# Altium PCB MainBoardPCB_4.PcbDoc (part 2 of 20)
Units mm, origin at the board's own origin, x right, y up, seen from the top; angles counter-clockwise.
Board outline 333.63 x 349.38 mm, 16 copper layers (L1, L2 (GND), L3 (Sign), L4 (GND), L5 (Sign), L6 (PWR/GND), L7(PWR/GND), L8 (Plane_GND), L9 (PWR/GND), L10 (PWR/GND), L11 (PWR/GND), L12 (Sign), L13 (GND), L14 (Sign), L15 (GND), L16), stack 2.502 mm thick; 2205 components, 1648 nets, 8314 pads, 3172 vias.
Unrouted connection lines stored in the file: 5141.
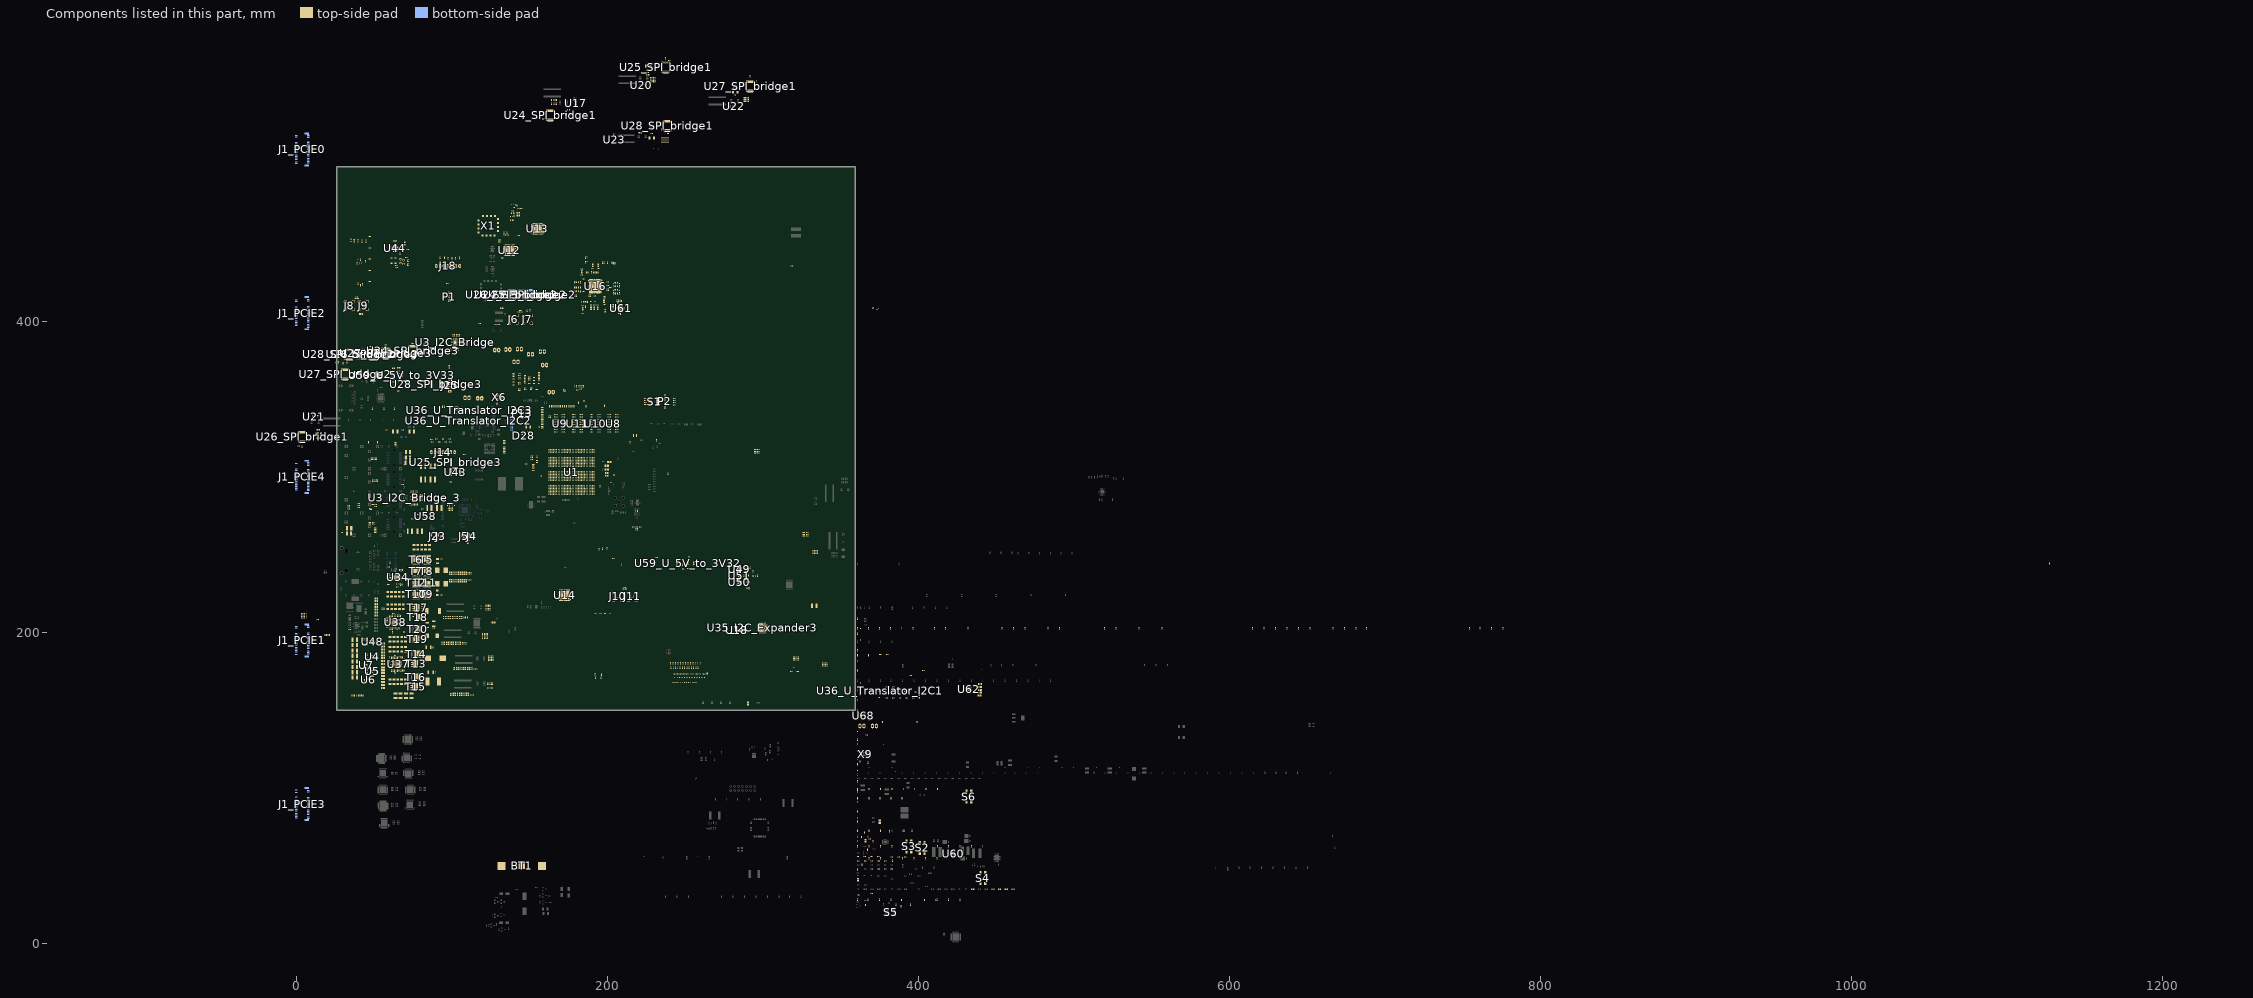
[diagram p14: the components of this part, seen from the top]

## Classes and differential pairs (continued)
differential pair class Diff_100: B223_Rx0 B223_Rx1 B223_Rx2 B223_Rx3 B223_Tx0_to_C B223_Tx0C_to_B B223_Tx1_to_C B223_Tx1C_to_B B223_Tx2_to_C B223_Tx2C_to_B B223_Tx3_to_C B223_Tx3C_to_B B224_Rx0 B224_Rx1 B224_Rx2 B224_Rx3 B224_Tx0_to_C B224_Tx0C_to_B B224_Tx1_to_C B224_Tx1C_to_B B224_Tx2_to_C B224_Tx2C_to_B B224_Tx3_to_C B224_Tx3C_to_B B225_Rx0 B225_Rx1 B225_Rx2 B225_Rx3 B225_Tx0_to_C B225_Tx0C_to_B B225_Tx1_to_C B225_Tx1C_to_B B225_Tx2_to_C B225_Tx2C_to_B B225_Tx3_to_C B225_Tx3C_to_B Bank223_MGTREF0_C Bank223_MGTREF1_C Bank224_MGTREF0_C Bank224_MGTREF1_C Bank225_MGTREF0_C Bank225_MGTREF1_C Bank505_MGTRREF0_C Bank505_MGTRREF2_C Bank505_MGTRREF3_C CLK_100 CLK_Fanout_In CLK_GTR_T1 CLK_GTR_T2 CLK_GTR_T3 CLK_Hi_Rail1 CLK_Hi_Rail1_SysRef CLK_Hi_Rail2 CLK_Hi_Rail2_SysRef CLK_M_OSC_In CLK_NVME_Conn CLK_Q223_T1 CLK_Q224_T1 CLK_Q225_T1 CLK_Q226_T1 CLK_SMA0 CLK_SMA0_C CLK_SMA1 CLK_SMA1_C CLK_SMA2 CLK_SMA2_C Data_2_RX_PCIE0 Data_2_RX_PCIE1 Data_2_RX_PCIE2 Data_2_RX_PCIE3 Data_2_TX_PCIE0 Data_2_TX_PCIE1 Data_2_TX_PCIE2 Data_2_TX_PCIE3 Data_3_RX_PCIE0 Data_3_RX_PCIE1 Data_3_RX_PCIE2 Data_3_RX_PCIE3 Data_3_TX_PCIE0 Data_3_TX_PCIE1 Data_3_TX_PCIE2 Data_3_TX_PCIE3 LTC6952_1_REF LTC6952_2_REF LTC6952_2_REF_SMA LTC6952_3_REF LTC6952_3_REF_SMA NVME_C_RX_O NVME_C_TX_1 NVME_C_TX_O NVMe_CLK NVMe_Rx_0 NVMe_Rx_1 NVMe_Tx_0 NVMe_Tx_1 Osc_in_Si53323_2 OSC_Out_DIV PCIE0_CLK PCIE0_Sync PCIE0_SysRef PCIE0_SysRef_FPGA PCIE1_CLK PCIE1_Sync PCIE1_SysRef PCIE1_SysRef_FPGA PCIE2_CLK PCIE2_Sync PCIE2_SysRef PCIE2_SysRef_FPGA PCIE3_CLK PCIE3_Sync PCIE3_SysRef PCIE3_SysRef_FPGA PCIE4_CLK PCIE4_Sync PCIE4_SysRef PCIE4_SysRef_FPGA RefClk_Si53323 SFP0_Rx SFP0_Tx SFP1_Rx SFP1_Tx SFP2_Rx SFP2_Tx SFP3_Rx SFP3_Tx SGMI_C_Rx SGMI_C_Tx SGMI_CLK_C_Out SGMI_CLK_Out SGMI_Rx SGMI_Tx Si53323_1_Q1 Si53323_1_Q2 Si53323_1_Q2_LVDS Si53323_2_CLK1 Si53323_2_Q1 Si53323_2_Q2 Si53323_2_Q2_LVDS SYNC_PCIE0 SYNC_PCIE1 SYNC_PCIE2 SYNC_PCIE3 SYNC_PCIE4 SYSREF_PCIE0 SYSREF_PCIE1 SYSREF_PCIE2 SYSREF_PCIE3 SYSREF_PCIE4 TD_A TD_B TD_C TD_D WR_LMK_CLK_HF1 WR_LMK_CLK_HF2 WR_LMK_CLK_IN WR_Source_CLK
channel class Translator_I2C: U_Translator_I2C1 U_Translator_I2C2 U_Translator_I2C3
channel class 5V_to_3V3: 5V_to_3V3_for_FTDI U_5V_to_3V32 U_5V_to_3V33
net class SYSREF: PCIE0_SysRef_N PCIE0_SysRef_P PCIE1_SysRef_N PCIE1_SysRef_P PCIE2_SysRef_N PCIE2_SysRef_P PCIE3_SysRef_N PCIE3_SysRef_P PCIE4_SysRef_N PCIE4_SysRef_P
net class Distr_to_Conn: PCIE0_CLK_P PCIE1_CLK_P PCIE2_CLK_P PCIE3_CLK_P PCIE4_CLK_P
net class SFP_diff: SFP0_Rx_N SFP0_Rx_P SFP0_Tx_N SFP0_Tx_P SFP1_Rx_N SFP1_Rx_P SFP1_Tx_N SFP1_Tx_P SFP2_Rx_N SFP2_Rx_P SFP2_Tx_N SFP2_Tx_P SFP3_Rx_N SFP3_Rx_P SFP3_Tx_N SFP3_Tx_P
net class Conn_to_C: B223_Tx0_to_C_N B223_Tx0_to_C_P B223_Tx1_to_C_N B223_Tx1_to_C_P B223_Tx2_to_C_N B223_Tx2_to_C_P B223_Tx3_to_C_N B223_Tx3_to_C_P B224_Tx0_to_C_N B224_Tx0_to_C_P B224_Tx1_to_C_N B224_Tx1_to_C_P B224_Tx2_to_C_N B224_Tx2_to_C_P B224_Tx3_to_C_N B224_Tx3_to_C_P B225_Tx0_to_C_N B225_Tx0_to_C_P B225_Tx1_to_C_N B225_Tx1_to_C_P B225_Tx2_to_C_N B225_Tx2_to_C_P B225_Tx3_to_C_N B225_Tx3_to_C_P Data_2_TX_PCIE0_N Data_2_TX_PCIE0_P Data_2_TX_PCIE1_N Data_2_TX_PCIE1_P Data_2_TX_PCIE2_N Data_2_TX_PCIE2_P Data_2_TX_PCIE3_N Data_2_TX_PCIE3_P Data_3_TX_PCIE0_N Data_3_TX_PCIE0_P Data_3_TX_PCIE1_N Data_3_TX_PCIE1_P Data_3_TX_PCIE2_N Data_3_TX_PCIE2_P Data_3_TX_PCIE3_N Data_3_TX_PCIE3_P
net class C_to_Bank225: B225_Tx0C_to_B_N B225_Tx0C_to_B_P B225_Tx1C_to_B_N B225_Tx1C_to_B_P B225_Tx2C_to_B_N B225_Tx2C_to_B_P B225_Tx3C_to_B_N B225_Tx3C_to_B_P
net class C_to_Bank224: B224_Tx0C_to_B_N B224_Tx0C_to_B_P B224_Tx1C_to_B_N B224_Tx1C_to_B_P B224_Tx2C_to_B_N B224_Tx2C_to_B_P B224_Tx3C_to_B_N B224_Tx3C_to_B_P
net class C_to_Bank223: B223_Rx0_N B223_Rx0_P B223_Rx1_N B223_Rx1_P B223_Rx2_N B223_Rx2_P B223_Rx3_N B223_Rx3_P B223_Tx0C_to_B_N B223_Tx0C_to_B_P B223_Tx1C_to_B_N B223_Tx1C_to_B_P B223_Tx2C_to_B_N B223_Tx2C_to_B_P B223_Tx3C_to_B_N B223_Tx3C_to_B_P
net class Bank_to_Conn: B223_Rx0_N B223_Rx0_P B223_Rx1_N B223_Rx1_P B223_Rx2_N B223_Rx2_P B223_Rx3_N B223_Rx3_P B224_Rx0_N B224_Rx0_P B224_Rx1_N B224_Rx1_P B224_Rx2_N B224_Rx2_P B224_Rx3_N B224_Rx3_P B225_Rx0_N B225_Rx0_P B225_Rx1_N B225_Rx1_P B225_Rx2_N B225_Rx2_P B225_Rx3_N B225_Rx3_P Data_2_RX_PCIE0_N Data_2_RX_PCIE0_P Data_2_RX_PCIE1_N Data_2_RX_PCIE1_P Data_2_RX_PCIE2_N Data_2_RX_PCIE2_P Data_2_RX_PCIE3_N Data_2_RX_PCIE3_P Data_3_RX_PCIE0_N Data_3_RX_PCIE0_P Data_3_RX_PCIE1_N Data_3_RX_PCIE1_P Data_3_RX_PCIE2_N Data_3_RX_PCIE2_P Data_3_RX_PCIE3_N Data_3_RX_PCIE3_P
component class U_Translator_I2C3: TP60_U_Translator_I2C3 TP61_U_Translator_I2C3 U36_U_Translator_I2C3
component class U_Translator_I2C2: TP60_U_Translator_I2C2 TP61_U_Translator_I2C2 U36_U_Translator_I2C2
component class U_Translator_I2C1: TP60_U_Translator_I2C1 TP61_U_Translator_I2C1 U36_U_Translator_I2C1
component class U_TPS7A88_5V_Dual_3: C572 C573 C574 C575 C576 C577 C578 C579 R436 R437 R438 R439 R440 R441 U61
component class U_LT3042_12V_5V_LNLDO: C580 C581 C582 C583 C584 FB34 R442 R443 R444 R445 U62
component class U_ADP1741_3: C568 C569 C570 C571 FB33 R433 R434 U60
component class U_5V_to_3V33: C563_U_5V_to_3V33 C564_U_5V_to_3V33 C565_U_5V_to_3V33 C566_U_5V_to_3V33 C567_U_5V_to_3V33 R430_U_5V_to_3V33 R431_U_5V_to_3V33 R432_U_5V_to_3V33 U59_U_5V_to_3V33
component class U_5V_to_3V32: C563_U_5V_to_3V32 C564_U_5V_to_3V32 C565_U_5V_to_3V32 C566_U_5V_to_3V32 C567_U_5V_to_3V32 R430_U_5V_to_3V32 R431_U_5V_to_3V32 R432_U_5V_to_3V32 U59_U_5V_to_3V32
component class SPI_bridge3: R231_SPI_bridge3 R232_SPI_bridge3 R233_SPI_bridge3 R234_SPI_bridge3 R235_SPI_bridge3 R236_SPI_bridge3 R237_SPI_bridge3 R238_SPI_bridge3 R239_SPI_bridge3 R240_SPI_bridge3 TP50_SPI_bridge3 TP51_SPI_bridge3 TP52_SPI_bridge3 TP53_SPI_bridge3 TP56_SPI_bridge3 TP57_SPI_bridge3 TP58_SPI_bridge3 TP59_SPI_bridge3 U24_SPI_bridge3 U25_SPI_bridge3 U26_SPI_bridge3 U27_SPI_bridge3 U28_SPI_bridge3
component class Ram_Power: C219 C220 C221 C222 C223 C224 C225 C226 C227 C228 C229 C230 C231 C232 C233 C234 C235 C236 C237 C238 C239 C240 C241 C242 C243 C244 C245 C246 C247 C248 C249 C250 C251 C252 C253 C254 C255 C256 C257 C258 C259 C260 C261 C262 C263 C264 C265 C266 C782 C783 C784 C785 C786 C787 C788 C789 R165 R166 R167 R168 R169 R170 R171 R172
component class PS_Config: C531 C532 C533 C534 C535 C536 D5 D6 D7 D8 D9 D10 D11 D12 P2 P3 P4 P5 R346 R347 R348 R349 R350 R351 R352 R353 R354 R355 R356 R357 R358 R359 R360 R361 R367 R368 R369 R370 R371 R372 R373 R374 R375 R716 R717 R718 R719 R720 S1 S2 S3 S4 U43 U44 X5 X6
component class IMU: C561 C562 R425 R426 R429 R600 R601 U58
component class GTR: C525 C526 C527 C528 C529 C530 C649 C651 C653 C677 C715 C716 C717 C718 R69 R70 R126
component class "Bank 225": C291 C292 C293 C294 C295 C296 C297 C298 C299 C300 C301 C302
component class "Bank 224": C279 C280 C281 C282 C283 C284 C285 C286 C287 C288 C289 C290
component class "Bank 223": C267 C268 C269 C270 C271 C272 C273 C274 C275 C276 C277 C278
component class U_Power_Ethernet: C550 C551 C552 C553 C554 C555 C654 C655 C656 C657 R391 R392 R393 R394 R396 R397 R399 R632 R633 R634 U49 U50 U51 U68
component class U_Power_ADP1850_Dual_2: C430 C431 C432 C433 C434 C435 C436 C437 C438 C439 C440 C441 C442 C443 C444 C445 C446 C447 C448 C449 C450 C451 C452 C453 C454 C455 C456 C457 C458 C459 C460 C461 C462 C463 C464 C465 C466 C467 C468 C469 C470 C548 C549 C645 C646 C647 C648 C650 C652 L19 L20 R302 R303 R306 R307 R310 R312 R313 R314 R315 R316 R317 R318 R625 R626 R627 R628 R629 R631 R686 R687 T17 T18 T19 T20 U38
component class U_HI_Curr_ADP1850_3: C389 C390 C391 C392 C393 C394 C395 C396 C397 C398 C399 C400 C401 C402 C403 C404 C405 C406 C407 C408 C409 C410 C411 C412 C413 C414 C415 C416 C417 C418 C419 C420 C421 C422 C423 C424 C425 C426 C427 C428 C429 C637 C638 C639 C640 C641 C642 C643 C644 L11 L12 R285 R287 R288 R289 R290 R292 R293 R294 R295 R296 R297 R298 R299 R300 R619 R620 R621 R622 R623 R624 T13 T14 T15 T16 U37
component class "Zasilanie CLK": C55 C56 C57 C58 C59 C60 C61 C62 C63 C64 C65 C66 C67 C68 C69 C70 C71 C72 C73 C74 C75 C76 C77 C78 C79 C80 C81 C82 C83 C84 C85 C86 C87 C88 C89 C90 C91 C92 C93 C94 C95 C96 C97 C98 C99 C100 C101 C102 C103 C104 C105 C106 C107 C108 C109 C110 C111 C112 C113 C114 C115 C116 C117 C118 C119 C120 C121 C122 C123 C124 C125 C126 C127 C128 C129 C130 C131 C132 C133 C134 C135 C136 C137 C138 C139 C140 C141 C142 C143 C144 C145 C146 C147 C148 C149 C150 C151 C152 C153 C154 C155 C156 C157 C158 C159 C160 C161 C162 C163 C164 C165 C166 C167 C168 C169 C170 C171 C172 C173 C174 C175 C176 C177 C178 C179 C180 C181 C182 C183 C184 C185 C186 C187 C188 C189 C190 C191 C192 C193 C194 C195 C196 C197 C198 C199 C200 C201 C202 C203 C204 C205 C206 FB2 FB3 FB4 FB5 FB6 FB7 FB8 FB9 FB10 FB11 FB12 FB13 FB14 FB15 FB16 FB17 FB18 FB19 FB20 FB21 FB22 FB35 FB36 R738 R739 R740 R741 R742 R743 U16
component class PowerSelector: C4 C5 C6 C7 C8 C9 C10 C11 C12 C13 C14 C15 C16 C17 C18 C19 C20 C21 C22 C23 C24 C25 C26 C27 C28 C29 C30 C31 C32 C33 C34 C35 C766 C767 C768 C769 C770 C771 C772 C773 C774 C775 C776 C777 C778 C779 C780 C781 R11 R12 R13 R15 R17 R18 R19 R20 R21 R23 R25 R26 R27 R28 R29 R30 R630 R677 R678 R679 R680 R681 R682 R683 R684 R685 U4 U5 U6 U7 U48
channel class SPI_Muxes: SPI_bridge1 SPI_bridge2
channel class I2C_Expander: I2C_Expander4 I2C_Expander5
component class XilinxPower: B1 C627 C628 C629 C630 C631 C632 D28 FB38 FB39 FB40 FB41 FB42 J29 J30 R173 R276 R279 R282 R283 R286 R693 R694 R695 R696
component class "Xilinx Linux": J12 J13 J14 J15 J16 J17 J18 J19 J20 J21 J22 J23 J24 J25 P1 P13 R83 R84 R85 R86 R87 R88 R89 R90 R91 R92 R93 R94 R95 R96 R97 R98 R99 R100 R101 R102 R103 R104 R105 R106 R107 R108 R109 R110 R111 R112 R115 R116 R117 R118 R119 R120 R121 R122 R123 R362 R675 R737 R768 R769 R770 R771 R772 R773 R774 R775 R776 R777 R778 R779 R780 R781 R782 R783 R784 R785 R786 R787 R788 R789 R790 R791 R792 R793 R794 R795 R796 R797 R798 R799 R800 R801 R802 R803 R804 R805 R806 R807 R808 R809 R810 R811 R812 R813 R814 R815 R816 TP33 TP34 TP35 TP36 TP37 TP38 TP39 TP40 TP41 TP42
component class "WR CLK": C588 C589 C590 C591 C592 FB37 R1 R2 R125 R127 R128 R129 R130 R131 R132 R133 R134 R139 R311 R366 R498 R499 R540 R543 R544 R545 R692 S6 X9
component class U_HI_Curr_ADP1850_1: C345 C346 C347 C348 C349 C350 C351 C352 C353 C356 C357 C358 C359 C360 C361 C362 C363 C364 C365 C366 C367 C368 C369 C370 C371 C372 C373 C374 C375 C376 C377 C378 C379 C380 C381 C382 C383 C384 C385 C386 C387 C388 C633 C634 C635 C636 L9 L10 R268 R271 R272 R273 R275 R277 R278 R280 R610 R611 R612 R613 R614 R615 R616 T5 T6 T7 T8 T9 T10 T11 T12 U34
component class SPI_bridge2: R231_SPI_bridge2 R232_SPI_bridge2 R233_SPI_bridge2 R234_SPI_bridge2 R235_SPI_bridge2 R236_SPI_bridge2 R237_SPI_bridge2 R238_SPI_bridge2 R239_SPI_bridge2 R240_SPI_bridge2 TP50_SPI_bridge2 TP51_SPI_bridge2 TP52_SPI_bridge2 TP53_SPI_bridge2 TP54_SPI_bridge2 TP55_SPI_bridge2 TP56_SPI_bridge2 TP57_SPI_bridge2 TP58_SPI_bridge2 TP59_SPI_bridge2 U24_SPI_bridge2 U25_SPI_bridge2 U26_SPI_bridge2 U27_SPI_bridge2 U28_SPI_bridge2
component class SPI_bridge1: R231_SPI_bridge1 R232_SPI_bridge1 R233_SPI_bridge1 R234_SPI_bridge1 R235_SPI_bridge1 R236_SPI_bridge1 R237_SPI_bridge1 R238_SPI_bridge1 R239_SPI_bridge1 R240_SPI_bridge1 TP53_SPI_bridge1 TP56_SPI_bridge1 TP57_SPI_bridge1 TP58_SPI_bridge1 TP59_SPI_bridge1 U24_SPI_bridge1 U25_SPI_bridge1 U26_SPI_bridge1 U27_SPI_bridge1 U28_SPI_bridge1
component class SFP3: C215 C216 C217 C218 L7 L8 R155 R156 R157 R158 R161 R162 R163 R164
component class SFP2: C211 C212 C213 C214 L5 L6 R145 R146 R147 R148 R151 R152 R153 R154
component class SFP1: C207 C208 C209 C210 L3 L4 R135 R136 R137 R138 R141 R142 R143 R144
component class Ram: C36 R31 R32 R33 R34 R35 R36 R37 R38 R39 R40 R41 R42 R43 R44 R45 R46 R47 R48 R49 R50 R51 R52 R53 R54 R55 R56 R57 R58 R59 R60 R61 R62 R63 R64 U8 U9 U10 U11
component class Power4HighSpeed: R174 R175 R176 R177 R178 R179 R180 R181 R182 R183 R184 R185 R186 R187 R188 R189 R190 R191 R192 R193 R194 R195 R196 R197 R198 R199 R200 R201 R202 R203 R204 R205 R206 R207 R208 R209 R210 R211 R213 R215 R217 R219 R221 R222 R228 R602 R603 R604 R605 R606 U17 U20 U21 U22 U23
component class I2C_Expander3: C311_I2C_Expander3 U35_I2C_Expander3
component class Ext_GPIO: R241 R242 R243 R244 R281 R400 R428 R492 R493 R494 R495 R496 R497 R500 R501 R502 R503 R504 R505 R508 R509 R510 R511 R512 R513 R516 R517 R518 R519 R520 R521 R524 R525 R526 R527 R528 R529 R599 R697 R698 R699 R700 R701 R702 R703 R704 R705 R706 R707 R708 R832 R833 R834 R835 R836 R837 R838 R839 R840 R841 TP62 TP63 TP64 TP65 TP66 TP67 TP68 TP69 TP70 TP71 TP72 TP73 TP74 TP75 TP76 TP77 TP78 TP79 TP80 TP81 TP82 TP83 TP84 TP85 TP86 TP87 TP88
component class HiCurrent: C331 C332 R14 R16 R22 R24 R266 R267 R269 R304 R388 R389 R390 R561 R562 R563 R564 R565 R566 R567 R568 R569 R570 R571 R572 R573 R574 R575 R576 R577 R578 R579 R580 R581 R582 R583 R584 R585 R586 R587 R588 R589 R590 R591 R592 S5 U18
component class PCIE4: C1_PCIE4 C2_PCIE4 C3_PCIE4 D1_PCIE4 FB1_PCIE4 J1_PCIE4
component class PCIE3: C1_PCIE3 C2_PCIE3 C3_PCIE3 D1_PCIE3 FB1_PCIE3 J1_PCIE3
component class PCIE2: C1_PCIE2 C2_PCIE2 C3_PCIE2 D1_PCIE2 FB1_PCIE2 J1_PCIE2
component class PCIE1: C1_PCIE1 C2_PCIE1 C3_PCIE1 D1_PCIE1 FB1_PCIE1 J1_PCIE1
component class PCIE0: C1_PCIE0 C2_PCIE0 C3_PCIE0 D1_PCIE0 FB1_PCIE0 J1_PCIE0
component class ClockDistrib: C41 C42 C43 C44 C45 C46 C47 C48 C49 C50 C51 C52 C53 C54 C334 C335 C593 C594 J2 J3 J4 J5 J6 J7 J8 J9 J10 J11 R75 R76 R77 R78 R79 R80 R81 R82 R270 R532 R533 R534 R535 R536 R537 R539 TP19 TP20 U12 U13 U14 X1
channel class PCIe: PCIE0 PCIE1 PCIE2 PCIE3 PCIE4
channel class I2C_Bridge: I2C_Bridge I2C_Bridge_3
component class "Bank 226": U1
component class SFP0: C37 C38 C39 C40 L1 L2 R65 R66 R67 R68 R71 R72 R73 R74
component class I2C_Bridge_3: C303_I2C_Bridge_3 R3_I2C_Bridge_3 R4_I2C_Bridge_3 R5_I2C_Bridge_3 R6_I2C_Bridge_3 R7_I2C_Bridge_3 R8_I2C_Bridge_3 R9_I2C_Bridge_3 R10_I2C_Bridge_3 R223_I2C_Bridge_3 R224_I2C_Bridge_3 R225_I2C_Bridge_3 R226_I2C_Bridge_3 R227_I2C_Bridge_3 R558_I2C_Bridge_3 R559_I2C_Bridge_3 R560_I2C_Bridge_3 TP1_I2C_Bridge_3 TP2_I2C_Bridge_3 TP3_I2C_Bridge_3 TP4_I2C_Bridge_3 TP5_I2C_Bridge_3 TP6_I2C_Bridge_3 TP8_I2C_Bridge_3 TP9_I2C_Bridge_3 TP10_I2C_Bridge_3 TP11_I2C_Bridge_3 TP15_I2C_Bridge_3 TP16_I2C_Bridge_3 TP17_I2C_Bridge_3 TP18_I2C_Bridge_3 U3_I2C_Bridge_3
component class I2C_Bridge: C303_I2C_Bridge R3_I2C_Bridge R4_I2C_Bridge R5_I2C_Bridge R6_I2C_Bridge R7_I2C_Bridge R8_I2C_Bridge R9_I2C_Bridge R10_I2C_Bridge R223_I2C_Bridge R224_I2C_Bridge R225_I2C_Bridge R226_I2C_Bridge R227_I2C_Bridge R558_I2C_Bridge R559_I2C_Bridge R560_I2C_Bridge TP1_I2C_Bridge TP2_I2C_Bridge TP3_I2C_Bridge TP4_I2C_Bridge TP5_I2C_Bridge TP6_I2C_Bridge TP8_I2C_Bridge TP9_I2C_Bridge TP10_I2C_Bridge TP11_I2C_Bridge TP15_I2C_Bridge TP16_I2C_Bridge TP17_I2C_Bridge TP18_I2C_Bridge U3_I2C_Bridge
differential pair USB_TX: +USB_TX_P -USB_TX_N
differential pair USB_TX_C: +USB_TX_C_P -USB_TX_C_N
differential pair USB_RX: +USB_RX_P -USB_RX_N
differential pair USB_RX_C: +USB_RX_C_P -USB_RX_C_N
differential pair USB_D: +USB_D_P -USB_D_N
differential pair TD_D: +TD_D_P -TD_D_N
differential pair TD_C: +TD_C_P -TD_C_N
differential pair TD_B: +TD_B_P -TD_B_N
differential pair TD_A: +TD_A_P -TD_A_N
differential pair SGMI_Tx: +SGMI_Tx_P -SGMI_Tx_N
differential pair SGMI_Rx: +SGMI_Rx_P -SGMI_Rx_N
differential pair SGMI_C_Tx: +SGMI_C_Tx_P -SGMI_C_Tx_N
differential pair SGMI_C_Rx: +SGMI_C_Rx_P -SGMI_C_Rx_N
differential pair NVMe_Tx_1: +NVMe_Tx_1_P -NVMe_Tx_1_N
differential pair NVMe_Tx_0: +NVMe_Tx_0_P -NVMe_Tx_0_N
differential pair NVMe_Rx_1: +NVMe_Rx_1_P -NVMe_Rx_1_N
differential pair NVMe_Rx_0: +NVMe_Rx_0_P -NVMe_Rx_0_N
differential pair DDR4_DQS_8: +DDR4_DQS_8_P -DDR4_DQS_8_N
differential pair DDR4_DQS_4: +DDR4_DQS_4_P -DDR4_DQS_4_N
differential pair NVME_C_TX_O: +NVME_C_TX_O_P -NVME_C_TX_O_N
differential pair NVME_C_TX_1: +NVME_C_TX_1_P -NVME_C_TX_1_N
differential pair NVME_C_RX_O: +NVME_C_RX_O_P -NVME_C_RX_O_N
differential pair WR_Source_CLK: +WR_Source_CLK_P -WR_Source_CLK_N
differential pair WR_LMK_CLK_IN: +WR_LMK_CLK_IN_P -WR_LMK_CLK_IN_N
differential pair WR_LMK_CLK_HF2: +WR_LMK_CLK_HF2_P -WR_LMK_CLK_HF2_N
differential pair WR_LMK_CLK_HF1: +WR_LMK_CLK_HF1_P -WR_LMK_CLK_HF1_N
differential pair PCIE4_SysRef_FPGA: +PCIE4_SysRef_FPGA_P -PCIE4_SysRef_FPGA_N
differential pair PCIE3_SysRef_FPGA: +PCIE3_SysRef_FPGA_P -PCIE3_SysRef_FPGA_N
differential pair PCIE2_SysRef_FPGA: +PCIE2_SysRef_FPGA_P -PCIE2_SysRef_FPGA_N
differential pair PCIE1_SysRef_FPGA: +PCIE1_SysRef_FPGA_P -PCIE1_SysRef_FPGA_N
differential pair PCIE0_SysRef_FPGA: +PCIE0_SysRef_FPGA_P -PCIE0_SysRef_FPGA_N
differential pair CLK_Fanout_In: +CLK_Fanout_In_P -CLK_Fanout_In_N
differential pair LTC6952_3_REF: +LTC6952_3_REF_P -LTC6952_3_REF_N
differential pair LTC6952_3_REF_SMA: +LTC6952_3_REF_SMA_P -LTC6952_3_REF_SMA_N
differential pair LTC6952_2_REF: +LTC6952_2_REF_P -LTC6952_2_REF_N
differential pair LTC6952_2_REF_SMA: +LTC6952_2_REF_SMA_P -LTC6952_2_REF_SMA_N
differential pair LTC6952_1_REF: +LTC6952_1_REF_P -LTC6952_1_REF_N
differential pair CLK_NVME_Conn: +CLK_NVME_Conn_P -CLK_NVME_Conn_N
differential pair CLK_Hi_Rail2: +CLK_Hi_Rail2_P -CLK_Hi_Rail2_N
differential pair CLK_Hi_Rail2_SysRef: +CLK_Hi_Rail2_SysRef_P -CLK_Hi_Rail2_SysRef_N
differential pair CLK_Hi_Rail1: +CLK_Hi_Rail1_P -CLK_Hi_Rail1_N
differential pair CLK_Hi_Rail1_SysRef: +CLK_Hi_Rail1_SysRef_P -CLK_Hi_Rail1_SysRef_N
differential pair CLK_GTR_T3: +CLK_GTR_T3_P -CLK_GTR_T3_N
differential pair CLK_GTR_T2: +CLK_GTR_T2_P -CLK_GTR_T2_N
differential pair CLK_GTR_T1: +CLK_GTR_T1_P -CLK_GTR_T1_N
differential pair Si53323_2_Q2_LVDS: +Si53323_2_Q2_LVDS_P -Si53323_2_Q2_LVDS_N
differential pair Si53323_1_Q2_LVDS: +Si53323_1_Q2_LVDS_P -Si53323_1_Q2_LVDS_N
differential pair Si53323_2_CLK1: +Si53323_2_CLK1_P -Si53323_2_CLK1_N
differential pair OSC_Out_DIV: +OSC_Out_DIV_P -OSC_Out_DIV_N
differential pair Osc_in_Si53323_2: +Osc_in_Si53323_2_P -Osc_in_Si53323_2_N
differential pair CLK_SMA2: +CLK_SMA2_P -CLK_SMA2_N
differential pair CLK_SMA2_C: +CLK_SMA2_C_P -CLK_SMA2_C_N
differential pair CLK_SMA1: +CLK_SMA1_P -CLK_SMA1_N
differential pair CLK_SMA1_C: +CLK_SMA1_C_P -CLK_SMA1_C_N
differential pair CLK_SMA0: +CLK_SMA0_P -CLK_SMA0_N
differential pair CLK_SMA0_C: +CLK_SMA0_C_P -CLK_SMA0_C_N
differential pair DDR4_DQS_7: +DDR4_DQS_7_P -DDR4_DQS_7_N
differential pair DDR4_DQS_6: +DDR4_DQS_6_P -DDR4_DQS_6_N
differential pair DDR4_DQS_5: +DDR4_DQS_5_P -DDR4_DQS_5_N
differential pair DDR4_DQS_3: +DDR4_DQS_3_P -DDR4_DQS_3_N
differential pair DDR4_DQS_2: +DDR4_DQS_2_P -DDR4_DQS_2_N
differential pair DDR4_DQS_1: +DDR4_DQS_1_P -DDR4_DQS_1_N
differential pair DDR4_DQS_0: +DDR4_DQS_0_P -DDR4_DQS_0_N
differential pair DDR4_CK: +DDR4_CK_P -DDR4_CK_N
differential pair Si53323_2_Q2: +Si53323_2_Q2_P -Si53323_2_Q2_N
differential pair Si53323_2_Q1: +Si53323_2_Q1_P -Si53323_2_Q1_N
differential pair Si53323_1_Q2: +Si53323_1_Q2_P -Si53323_1_Q2_N
differential pair Si53323_1_Q1: +Si53323_1_Q1_P -Si53323_1_Q1_N
differential pair RefClk_Si53323: +RefClk_Si53323_P -RefClk_Si53323_N
differential pair CLK_Q226_T1: +CLK_Q226_T1_P -CLK_Q226_T1_N
differential pair CLK_Q225_T1: +CLK_Q225_T1_P -CLK_Q225_T1_N
differential pair CLK_Q224_T1: +CLK_Q224_T1_P -CLK_Q224_T1_N
differential pair CLK_Q223_T1: +CLK_Q223_T1_P -CLK_Q223_T1_N
differential pair Bank505_MGTRREF3_C: +Bank505_MGTRREF3_C_P -Bank505_MGTRREF3_C_N
differential pair Bank505_MGTRREF2_C: +Bank505_MGTRREF2_C_P -Bank505_MGTRREF2_C_N
differential pair Bank505_MGTRREF0_C: +Bank505_MGTRREF0_C_P -Bank505_MGTRREF0_C_N
differential pair Bank225_MGTREF1_C: +Bank225_MGTREF1_C_P -Bank225_MGTREF1_C_N
differential pair Bank225_MGTREF0_C: +Bank225_MGTREF0_C_P -Bank225_MGTREF0_C_N
differential pair Bank224_MGTREF1_C: +Bank224_MGTREF1_C_P -Bank224_MGTREF1_C_N
differential pair Bank224_MGTREF0_C: +Bank224_MGTREF0_C_P -Bank224_MGTREF0_C_N
differential pair Bank223_MGTREF1_C: +Bank223_MGTREF1_C_P -Bank223_MGTREF1_C_N
differential pair Bank223_MGTREF0_C: +Bank223_MGTREF0_C_P -Bank223_MGTREF0_C_N
differential pair SYNC_PCIE4: +SYNC_PCIE4_P -SYNC_PCIE4_N
differential pair SYNC_PCIE3: +SYNC_PCIE3_P -SYNC_PCIE3_N
differential pair SYNC_PCIE2: +SYNC_PCIE2_P -SYNC_PCIE2_N
differential pair SYNC_PCIE1: +SYNC_PCIE1_P -SYNC_PCIE1_N
differential pair SYNC_PCIE0: +SYNC_PCIE0_P -SYNC_PCIE0_N
differential pair PCIE4_SysRef: +PCIE4_SysRef_P -PCIE4_SysRef_N
differential pair PCIE3_SysRef: +PCIE3_SysRef_P -PCIE3_SysRef_N
differential pair PCIE2_SysRef: +PCIE2_SysRef_P -PCIE2_SysRef_N
differential pair PCIE1_SysRef: +PCIE1_SysRef_P -PCIE1_SysRef_N
differential pair PCIE0_SysRef: +PCIE0_SysRef_P -PCIE0_SysRef_N
differential pair SFP3_Tx: +SFP3_Tx_P -SFP3_Tx_N
differential pair SFP3_Rx: +SFP3_Rx_P -SFP3_Rx_N
differential pair SFP2_Tx: +SFP2_Tx_P -SFP2_Tx_N
differential pair SFP2_Rx: +SFP2_Rx_P -SFP2_Rx_N
differential pair SFP1_Tx: +SFP1_Tx_P -SFP1_Tx_N
differential pair SFP1_Rx: +SFP1_Rx_P -SFP1_Rx_N
differential pair SFP0_Tx: +SFP0_Tx_P -SFP0_Tx_N
differential pair SFP0_Rx: +SFP0_Rx_P -SFP0_Rx_N
differential pair PCIE4_CLK: +PCIE4_CLK_P -PCIE4_CLK_N
differential pair PCIE3_CLK: +PCIE3_CLK_P -PCIE3_CLK_N
differential pair PCIE2_CLK: +PCIE2_CLK_P -PCIE2_CLK_N
differential pair PCIE1_CLK: +PCIE1_CLK_P -PCIE1_CLK_N
differential pair PCIE0_CLK: +PCIE0_CLK_P -PCIE0_CLK_N
differential pair B225_Tx3C_to_B: +B225_Tx3C_to_B_P -B225_Tx3C_to_B_N
differential pair B225_Tx3_to_C: +B225_Tx3_to_C_P -B225_Tx3_to_C_N
differential pair B225_Tx2C_to_B: +B225_Tx2C_to_B_P -B225_Tx2C_to_B_N
differential pair B225_Tx2_to_C: +B225_Tx2_to_C_P -B225_Tx2_to_C_N
differential pair B225_Tx1C_to_B: +B225_Tx1C_to_B_P -B225_Tx1C_to_B_N
differential pair B225_Tx1_to_C: +B225_Tx1_to_C_P -B225_Tx1_to_C_N
differential pair B225_Tx0C_to_B: +B225_Tx0C_to_B_P -B225_Tx0C_to_B_N
differential pair B225_Tx0_to_C: +B225_Tx0_to_C_P -B225_Tx0_to_C_N
differential pair B225_Rx3: +B225_Rx3_P -B225_Rx3_N
differential pair B225_Rx2: +B225_Rx2_P -B225_Rx2_N
differential pair B225_Rx1: +B225_Rx1_P -B225_Rx1_N
differential pair B225_Rx0: +B225_Rx0_P -B225_Rx0_N
differential pair B224_Tx3C_to_B: +B224_Tx3C_to_B_P -B224_Tx3C_to_B_N
differential pair B224_Tx3_to_C: +B224_Tx3_to_C_P -B224_Tx3_to_C_N
differential pair B224_Tx2C_to_B: +B224_Tx2C_to_B_P -B224_Tx2C_to_B_N
differential pair B224_Tx2_to_C: +B224_Tx2_to_C_P -B224_Tx2_to_C_N
differential pair B224_Tx1C_to_B: +B224_Tx1C_to_B_P -B224_Tx1C_to_B_N
differential pair B224_Tx1_to_C: +B224_Tx1_to_C_P -B224_Tx1_to_C_N
differential pair B224_Tx0C_to_B: +B224_Tx0C_to_B_P -B224_Tx0C_to_B_N
differential pair B224_Tx0_to_C: +B224_Tx0_to_C_P -B224_Tx0_to_C_N
differential pair B224_Rx3: +B224_Rx3_P -B224_Rx3_N
differential pair B224_Rx2: +B224_Rx2_P -B224_Rx2_N
differential pair B224_Rx1: +B224_Rx1_P -B224_Rx1_N
differential pair B224_Rx0: +B224_Rx0_P -B224_Rx0_N
differential pair B223_Tx3C_to_B: +B223_Tx3C_to_B_P -B223_Tx3C_to_B_N
differential pair B223_Tx3_to_C: +B223_Tx3_to_C_P -B223_Tx3_to_C_N
differential pair B223_Tx2C_to_B: +B223_Tx2C_to_B_P -B223_Tx2C_to_B_N
differential pair B223_Tx2_to_C: +B223_Tx2_to_C_P -B223_Tx2_to_C_N
differential pair B223_Tx1C_to_B: +B223_Tx1C_to_B_P -B223_Tx1C_to_B_N
differential pair B223_Tx1_to_C: +B223_Tx1_to_C_P -B223_Tx1_to_C_N
differential pair B223_Tx0C_to_B: +B223_Tx0C_to_B_P -B223_Tx0C_to_B_N
differential pair B223_Tx0_to_C: +B223_Tx0_to_C_P -B223_Tx0_to_C_N
differential pair B223_Rx3: +B223_Rx3_P -B223_Rx3_N
differential pair B223_Rx2: +B223_Rx2_P -B223_Rx2_N
differential pair B223_Rx1: +B223_Rx1_P -B223_Rx1_N
differential pair B223_Rx0: +B223_Rx0_P -B223_Rx0_N
differential pair Data_3_TX_PCIE3: +Data_3_TX_PCIE3_P -Data_3_TX_PCIE3_N
differential pair Data_3_TX_PCIE2: +Data_3_TX_PCIE2_P -Data_3_TX_PCIE2_N
differential pair Data_3_TX_PCIE1: +Data_3_TX_PCIE1_P -Data_3_TX_PCIE1_N
differential pair Data_3_TX_PCIE0: +Data_3_TX_PCIE0_P -Data_3_TX_PCIE0_N
differential pair Data_3_RX_PCIE3: +Data_3_RX_PCIE3_P -Data_3_RX_PCIE3_N
differential pair Data_3_RX_PCIE2: +Data_3_RX_PCIE2_P -Data_3_RX_PCIE2_N
differential pair Data_3_RX_PCIE1: +Data_3_RX_PCIE1_P -Data_3_RX_PCIE1_N
differential pair Data_3_RX_PCIE0: +Data_3_RX_PCIE0_P -Data_3_RX_PCIE0_N
differential pair Data_2_TX_PCIE3: +Data_2_TX_PCIE3_P -Data_2_TX_PCIE3_N
differential pair Data_2_TX_PCIE2: +Data_2_TX_PCIE2_P -Data_2_TX_PCIE2_N
differential pair Data_2_TX_PCIE1: +Data_2_TX_PCIE1_P -Data_2_TX_PCIE1_N
differential pair Data_2_TX_PCIE0: +Data_2_TX_PCIE0_P -Data_2_TX_PCIE0_N
differential pair Data_2_RX_PCIE3: +Data_2_RX_PCIE3_P -Data_2_RX_PCIE3_N
differential pair Data_2_RX_PCIE2: +Data_2_RX_PCIE2_P -Data_2_RX_PCIE2_N
differential pair Data_2_RX_PCIE1: +Data_2_RX_PCIE1_P -Data_2_RX_PCIE1_N
differential pair Data_2_RX_PCIE0: +Data_2_RX_PCIE0_P -Data_2_RX_PCIE0_N

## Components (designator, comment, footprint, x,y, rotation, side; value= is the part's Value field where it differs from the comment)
B1 "TS920E-FL27E" Battery 217.703,326.631 r0 top
BT1 "79523141" 79523141 145.009,49.886 r0 top
C1_PCIE0 "100nF" "CAP 0402/1005 RF" 175.118,537.889 r0 top (schematic designator C1)
C1_PCIE1 "100nF" "CAP 0402/1005 RF" 225.975,559.952 r180 top (schematic designator C1)
C1_PCIE2 "100nF" "CAP 0402/1005 RF" 13.819,208.225 r0 top (schematic designator C1)
C1_PCIE3 "100nF" "CAP 0402/1005 RF" 281.991,545.668 r180 top (schematic designator C1)
C1_PCIE4 "100nF" "CAP 0402/1005 RF" 228.564,520.7 r180 top (schematic designator C1)
C2_PCIE0 "2.2uF" "CAP 1206/3216 - 0.8MM" 174.864,533.19 r0 top (schematic designator C2)
C2_PCIE1 "2.2uF" "CAP 1206/3216 - 0.8MM" 226.238,564.143 r180 top (schematic designator C2)
C2_PCIE2 "2.2uF" "CAP 1206/3216 - 0.8MM" 14.297,327.631 r0 top (schematic designator C2)
C2_PCIE3 "2.2uF" "CAP 1206/3216 - 0.8MM" 282.118,547.319 r180 top (schematic designator C2)
C2_PCIE4 "2.2uF" "CAP 1206/3216 - 0.8MM" 228.691,517.817 r180 top (schematic designator C2)
C3_PCIE0 "4.7uF" "CAP 0603/1608 RF" 174.991,536.111 r0 top (schematic designator C3)
C3_PCIE1 "4.7uF" "CAP 0603/1608 RF" 226.111,561.476 r180 top (schematic designator C3)
C3_PCIE2 "4.7uF" "CAP 0603/1608 RF" 14.053,324.71 r0 top (schematic designator C3)
C3_PCIE3 "4.7uF" "CAP 0603/1608 RF" 282.118,551.51 r180 top (schematic designator C3)
C3_PCIE4 "4.7uF" "CAP 0603/1608 RF" 228.066,525.145 r180 top (schematic designator C3)
C4 "22uF" "CAP 1210/3225 - 1MM" 37.591,170.893 r180 top
C5 "22uF" "CAP 1210/3225 - 1MM" 37.591,174.348 r180 top
C6 "22uF" "CAP 1210/3225 - 1MM" 37.591,181.257 r180 top
C7 "22uF" "CAP 1210/3225 - 1MM" 37.591,177.802 r180 top
C8 "100nF" "CAP 0402/1005 RF" 39.985,159.376 r270 top
C9 "100nF" "CAP 0402/1005 RF" 42.83,159.376 r270 top
C10 "100nF" "CAP 0402/1005 RF" 41.901,159.376 r270 top
C11 "100nF" "CAP 0402/1005 RF" 40.965,159.376 r270 top
C12 "22uF" "CAP 1210/3225 - 1MM" 37.51,184.916 r180 top
C13 "22uF" "CAP 1210/3225 - 1MM" 37.51,191.806 r180 top
C14 "22uF" "CAP 1210/3225 - 1MM" 37.51,195.251 r180 top
C15 "22uF" "CAP 1210/3225 - 1MM" 37.51,188.361 r180 top
C16 "100nF" "CAP 0402/1005 RF" 18.529,198.266 r270 top
C17 "100nF" "CAP 0402/1005 RF" 21.364,198.266 r270 top
C18 "100nF" "CAP 0402/1005 RF" 20.365,198.266 r270 top
C19 "100nF" "CAP 0402/1005 RF" 19.46,198.266 r270 top
C20 "10uF" "CAP 0805/2012 RF" 55.719,164.138 r180 top
C21 "10uF" "CAP 0805/2012 RF" 55.746,169.941 r180 top
C22 "10uF" "CAP 0805/2012 RF" 55.746,168.043 r180 top
C23 "10uF" "CAP 0805/2012 RF" 55.746,175.635 r180 top
C24 "4.7uF" "CAP 0805/2012 RF" 55.746,171.839 r180 top
C25 "4.7uF" "CAP 0805/2012 RF" 55.746,173.737 r180 top
C26 "4.7uF" "CAP 0805/2012 RF" 55.746,177.532 r180 top
C27 "4.7uF" "CAP 0805/2012 RF" 55.746,166.145 r180 top
C28 "10uF" "CAP 0805/2012 RF" 55.758,187.161 r180 top
C29 "10uF" "CAP 0805/2012 RF" 55.758,185.263 r180 top
C30 "10uF" "CAP 0805/2012 RF" 55.758,181.467 r180 top
C31 "10uF" "CAP 0805/2012 RF" 55.758,179.569 r180 top
C32 "4.7uF" "CAP 0805/2012 RF" 55.758,183.365 r180 top
C33 "4.7uF" "CAP 0805/2012 RF" 55.758,189.059 r180 top
C34 "4.7uF" "CAP 0805/2012 RF" 55.758,190.956 r180 top
C35 "4.7uF" "CAP 0805/2012 RF" 55.784,192.899 r180 top
C36 "10nF" "CAP 0402/1005 RF" 155.956,331.965 r180 top
C37 "100nF" "CAP 0402/1005 RF" 29.299,264.312 r0 top
C38 "22uF" "CAP 1210/3225 - 1MM" 33.871,263.55 r0 top
C39 "100nF" "CAP 0402/1005 RF" 38.57,263.423 r0 top
C40 "22uF" "CAP 1210/3225 - 1MM" 33.923,266.979 r0 top
C41 "1uF" "CAP 0402/1005 RF" 90.054,258.034 r270 top
C42 "1uF" "CAP 0402/1005 RF" 90.954,258.034 r270 top
C43 "1uF" "CAP 0402/1005 RF" 110.881,257.529 r270 top
C44 "1uF" "CAP 0402/1005 RF" 109.981,257.529 r270 top
C45 "5.6nF" "CAP 0402/1005 RF" 131.053,452.303 r270 top
C46 "200pF" "CAP 0402/1005 RF" 130.153,452.303 r270 top
C47 "1uF" "CAP 0402/1005 RF" 144.718,406.037 r0 top
C48 "1uF" "CAP 0402/1005 RF" 143.038,406.037 r180 top
C49 "1uF" "CAP 0402/1005 RF" 39.677,414.757 r0 top
C50 "1uF" "CAP 0402/1005 RF" 37.997,414.757 r180 top
C51 "1uF" "CAP 0402/1005 RF" 212.021,227.978 r0 top
C52 "1uF" "CAP 0402/1005 RF" 210.341,227.978 r180 top
C53 "1uF" "CAP 0402/1005 RF" 218.46,267.242 r90 top
C54 "1uF" "CAP 0402/1005 RF" 219.36,267.242 r90 top
C55 "0.1µF" "CAP 0201/0603 RF" 100.292,283.421 r90 top
C56 "0.1µF" "CAP 0201/0603 RF" 98.387,283.421 r90 top
C57 "0.1µF" "CAP 0201/0603 RF" 97.244,281.77 r270 top
C58 "10µF" "CAP 0402/1005 RF" 98.387,281.776 r270 top
C59 "0.1µF" "CAP 0201/0603 RF" 144.138,472.357 r90 top
C60 "0.1µF" "CAP 0201/0603 RF" 143.249,472.357 r90 top
C61 "0.1µF" "CAP 0201/0603 RF" 139.808,475.674 r90 top
C62 "10µF" "CAP 0402/1005 RF" 138.535,475.544 r90 top
C63 "100nF" "CAP 0402/1005 RF" 189.1,412.326 r270 top
C64 "100nF" "CAP 0402/1005 RF" 198.227,415.882 r0 top
C65 "0.1µF" "CAP 0201/0603 RF" 101.181,283.427 r90 top
C66 "0.1µF" "CAP 0201/0603 RF" 97.498,283.427 r90 top
C67 "100nF" "CAP 0402/1005 RF" 192.49,415.882 r270 top
C68 "10nF" "CAP 0201/0603 RF" 101.689,281.776 r270 top
C69 "10µF" "CAP 0402/1005 RF" 100.292,281.776 r270 top
C70 "100nF" "CAP 0402/1005 RF" 189.99,412.326 r270 top
C71 "0.1µF" "CAP 0201/0603 RF" 140.201,472.369 r0 top
C72 "0.1µF" "CAP 0201/0603 RF" 140.068,473.258 r0 top
C73 "0.1µF" "CAP 0201/0603 RF" 138.795,472.369 r180 top
C74 "10µF" "CAP 0402/1005 RF" 139.185,470.972 r180 top
C75 "100nF" "CAP 0402/1005 RF" 200.241,420.766 r0 top
C76 "100nF" "CAP 0402/1005 RF" 200.241,422.994 r0 top
C77 "100nF" "CAP 0402/1005 RF" 184.62,421.266 r180 top
C78 "10uF" "CAP 0402/1005 RF" 191.49,415.882 r90 top
C79 "10uF" "CAP 0402/1005 RF" 192.99,431.425 r270 top
C80 "10uF" "CAP 0402/1005 RF" 186.585,431.425 r270 top
C81 "100nF" "CAP 0402/1005 RF" 184.62,419.266 r180 top
C82 "100nF" "CAP 0402/1005 RF" 200.241,425.266 r0 top
C83 "100nF" "CAP 0402/1005 RF" 184.62,426.113 r180 top
C84 "0.1µF" "CAP 0201/0603 RF" 137.788,467.67 r90 top
C85 "0.1µF" "CAP 0201/0603 RF" 144.9,472.357 r90 top
C86 "10nF" "CAP 0201/0603 RF" 138.804,467.676 r90 top
C87 "10µF" "CAP 0402/1005 RF" 139.947,467.676 r90 top
C88 "100nF" "CAP 0402/1005 RF" 184.62,427.113 r180 top
C89 "100nF" "CAP 0402/1005 RF" 193.99,431.425 r90 top
C90 "100nF" "CAP 0402/1005 RF" 191.05,431.425 r90 top
C91 "100nF" "CAP 0402/1005 RF" 191.99,431.425 r90 top
C92 "100nF" "CAP 0402/1005 RF" 200.241,419.766 r0 top
C93 "100nF" "CAP 0402/1005 RF" 191.986,412.326 r270 top
C94 "0.1µF" "CAP 0201/0603 RF" 145.662,472.363 r90 top
C95 "0.1µF" "CAP 0201/0603 RF" 142.36,472.363 r90 top
C96 "100nF" "CAP 0402/1005 RF" 187.585,431.425 r90 top
C97 "10nF" "CAP 0201/0603 RF" 140.963,474.519 r90 top
C98 "10µF" "CAP 0402/1005 RF" 141.852,474.519 r90 top
C99 "100nF" "CAP 0402/1005 RF" 183.537,412.395 r90 top
C100 "100nF" "CAP 0402/1005 RF" 207.734,424.749 r90 top
C101 "10uF" "CAP 0402/1005 RF" 187.347,412.404 r90 top
C102 "10uF" "CAP 0402/1005 RF" 203.788,424.749 r90 top
C103 "100nF" "CAP 0402/1005 RF" 198.227,410.931 r180 top
C104 "100nF" "CAP 0402/1005 RF" 178.769,425.156 r90 top
C105 "10uF" "CAP 0402/1005 RF" 198.227,414.877 r180 top
C106 "10uF" "CAP 0402/1005 RF" 182.715,425.156 r90 top
C107 "100nF" "CAP 0402/1005 RF" 193.769,406.475 r180 top
C108 "100nF" "CAP 0402/1005 RF" 183.528,433.758 r0 top
C109 "10uF" "CAP 0402/1005 RF" 193.769,410.421 r180 top
C110 "10uF" "CAP 0402/1005 RF" 183.528,429.812 r0 top
C111 "10nF" "CAP 0201/0603 RF" 244.752,167.951 r90 top
C112 "10nF" "CAP 0201/0603 RF" 245.979,167.951 r90 top
C113 "10nF" "CAP 0201/0603 RF" 250.89,167.951 r90 top
C114 "10nF" "CAP 0201/0603 RF" 254.573,167.951 r90 top
C115 "10nF" "CAP 0201/0603 RF" 255.801,167.951 r90 top
C116 "10nF" "CAP 0201/0603 RF" 253.345,167.951 r90 top
C117 "10nF" "CAP 0201/0603 RF" 243.524,167.951 r90 top
C118 "10nF" "CAP 0201/0603 RF" 242.296,167.951 r90 top
C119 "10nF" "CAP 0201/0603 RF" 249.662,167.951 r90 top
C120 "10nF" "CAP 0201/0603 RF" 257.028,167.951 r90 top
C121 "10nF" "CAP 0201/0603 RF" 247.207,167.951 r90 top
C122 "10nF" "CAP 0201/0603 RF" 248.435,167.951 r90 top
C123 "10nF" "CAP 0201/0603 RF" 252.118,167.951 r90 top
C124 "100nF" "CAP 0402/1005 RF" 189.49,406.475 r180 top
C125 "100nF" "CAP 0402/1005 RF" 194.38,437.98 r180 top
C126 "10uF" "CAP 0402/1005 RF" 189.49,410.421 r180 top
C127 "10uF" "CAP 0402/1005 RF" 194.38,434.034 r180 top
C128 "1uF" "CAP 0402/1005 RF" 246.531,171.368 r90 top
C129 "1uF" "CAP 0402/1005 RF" 254.502,171.368 r90 top
C130 "1uF" "CAP 0402/1005 RF" 248.125,171.368 r90 top
C131 "1uF" "CAP 0402/1005 RF" 256.096,171.368 r90 top
C132 "1uF" "CAP 0402/1005 RF" 260.879,171.368 r90 top
C133 "1uF" "CAP 0402/1005 RF" 243.343,171.368 r90 top
C134 "1uF" "CAP 0402/1005 RF" 251.314,171.368 r90 top
C135 "1uF" "CAP 0402/1005 RF" 249.72,171.368 r90 top
C136 "1uF" "CAP 0402/1005 RF" 257.69,171.368 r90 top
C137 "1uF" "CAP 0402/1005 RF" 262.473,171.368 r90 top
C138 "1uF" "CAP 0402/1005 RF" 244.937,171.368 r90 top
C139 "1uF" "CAP 0402/1005 RF" 252.908,171.368 r90 top
C140 "1uF" "CAP 0402/1005 RF" 259.284,171.368 r90 top
C141 "100nF" "CAP 0402/1005 RF" 207.774,420.229 r270 top
C142 "100nF" "CAP 0402/1005 RF" 190.56,437.98 r0 top
C143 "10uF" "CAP 0402/1005 RF" 203.828,420.229 r270 top
C144 "10uF" "CAP 0402/1005 RF" 190.56,434.034 r0 top
C145 "100nF" "CAP 0402/1005 RF" 207.734,422.604 r90 top
C146 "100nF" "CAP 0402/1005 RF" 207.774,418.032 r270 top
C147 "10uF" "CAP 0402/1005 RF" 203.788,422.604 r90 top
C148 "10uF" "CAP 0402/1005 RF" 203.828,418.032 r270 top
C149 "10nF" "CAP 0201/0603 RF" 257.361,173.521 r90 top
C150 "10nF" "CAP 0201/0603 RF" 260.98,173.521 r90 top
C151 "10nF" "CAP 0201/0603 RF" 256.457,173.521 r90 top
C152 "10nF" "CAP 0201/0603 RF" 259.171,173.521 r90 top
C153 "10nF" "CAP 0201/0603 RF" 254.648,173.521 r90 top
C154 "10nF" "CAP 0201/0603 RF" 260.075,173.521 r90 top
C155 "10nF" "CAP 0201/0603 RF" 255.552,173.521 r90 top
C156 "10nF" "CAP 0201/0603 RF" 258.266,173.521 r90 top
C157 "10nF" "CAP 0201/0603 RF" 253.743,173.521 r90 top
C158 "10nF" "CAP 0201/0603 RF" 263.631,173.533 r90 top
C159 "10nF" "CAP 0201/0603 RF" 262.789,173.521 r90 top
C160 "10nF" "CAP 0201/0603 RF" 264.393,173.533 r90 top
C161 "10nF" "CAP 0201/0603 RF" 261.884,173.521 r90 top
C162 "100nF" "CAP 0402/1005 RF" 178.905,421.824 r270 top
C163 "100nF" "CAP 0402/1005 RF" 191.596,406.475 r180 top
C164 "10uF" "CAP 0402/1005 RF" 182.715,421.824 r90 top
C165 "10uF" "CAP 0402/1005 RF" 191.596,410.421 r180 top
C166 "10nF" "CAP 0201/0603 RF" 242.803,173.521 r90 top
C167 "10nF" "CAP 0201/0603 RF" 246.666,173.521 r90 top
C168 "10nF" "CAP 0201/0603 RF" 250.529,173.521 r90 top
C169 "10nF" "CAP 0201/0603 RF" 243.576,173.521 r90 top
C170 "10nF" "CAP 0201/0603 RF" 247.439,173.521 r90 top
C171 "10nF" "CAP 0201/0603 RF" 244.348,173.521 r90 top
C172 "10nF" "CAP 0201/0603 RF" 248.211,173.521 r90 top
C173 "10nF" "CAP 0201/0603 RF" 252.074,173.521 r90 top
C174 "10nF" "CAP 0201/0603 RF" 245.893,173.521 r90 top
C175 "10nF" "CAP 0201/0603 RF" 248.984,173.521 r90 top
C176 "10nF" "CAP 0201/0603 RF" 251.302,173.521 r90 top
C177 "10nF" "CAP 0201/0603 RF" 245.121,173.521 r90 top
C178 "10nF" "CAP 0201/0603 RF" 249.756,173.521 r90 top
C179 "100nF" "CAP 0402/1005 RF" 178.669,419.175 r90 top
C180 "10uF" "CAP 0402/1005 RF" 182.715,419.175 r90 top
C181 "1uF" "CAP 0402/1005 RF" 258.424,177.198 r90 top
C182 "1uF" "CAP 0402/1005 RF" 240.898,177.198 r90 top
C183 "1uF" "CAP 0402/1005 RF" 249.661,177.198 r90 top
C184 "1uF" "CAP 0402/1005 RF" 242.359,177.198 r90 top
C185 "1uF" "CAP 0402/1005 RF" 251.122,177.198 r90 top
C186 "1uF" "CAP 0402/1005 RF" 248.201,177.198 r90 top
C187 "1uF" "CAP 0402/1005 RF" 256.964,177.198 r90 top
C188 "1uF" "CAP 0402/1005 RF" 243.819,177.198 r90 top
C189 "1uF" "CAP 0402/1005 RF" 252.582,177.198 r90 top
C190 "1uF" "CAP 0402/1005 RF" 246.74,177.198 r90 top
C191 "1uF" "CAP 0402/1005 RF" 255.503,177.198 r90 top
C192 "1uF" "CAP 0402/1005 RF" 245.28,177.198 r90 top
C193 "1uF" "CAP 0402/1005 RF" 254.043,177.198 r90 top
C194 "1uF" "CAP 0402/1005 RF" 248.588,180.137 r90 top
C195 "1uF" "CAP 0402/1005 RF" 258.142,180.137 r90 top
C196 "1uF" "CAP 0402/1005 RF" 254.957,180.137 r90 top
C197 "1uF" "CAP 0402/1005 RF" 246.995,180.137 r90 top
C198 "1uF" "CAP 0402/1005 RF" 259.734,180.137 r90 top
C199 "1uF" "CAP 0402/1005 RF" 253.365,180.137 r90 top
C200 "1uF" "CAP 0402/1005 RF" 251.772,180.137 r90 top
C201 "1uF" "CAP 0402/1005 RF" 256.549,180.137 r90 top
C202 "1uF" "CAP 0402/1005 RF" 250.18,180.137 r90 top
C203 "1uF" "CAP 0402/1005 RF" 240.626,180.137 r90 top
C204 "1uF" "CAP 0402/1005 RF" 243.811,180.137 r90 top
C205 "1uF" "CAP 0402/1005 RF" 242.219,180.137 r90 top
C206 "1uF" "CAP 0402/1005 RF" 245.403,180.137 r90 top
C207 "100nF" "CAP 0402/1005 RF" 57.874,330.225 r0 top
C208 "22uF" "CAP 1210/3225 - 1MM" 63.716,329.082 r0 top
C209 "100nF" "CAP 0402/1005 RF" 68.415,330.225 r0 top
C210 "22uF" "CAP 1210/3225 - 1MM" 74.13,329.082 r0 top
C211 "100nF" "CAP 0402/1005 RF" 68.415,295.046 r180 top
C212 "22uF" "CAP 1210/3225 - 1MM" 332.956,217.068 r0 top
C213 "100nF" "CAP 0402/1005 RF" 63.716,320.358 r0 top
C214 "22uF" "CAP 1210/3225 - 1MM" 71.717,309.016 r0 top
C215 "100nF" "CAP 0402/1005 RF" 63.716,322.136 r0 top
C216 "22uF" "CAP 1210/3225 - 1MM" 71.844,316.001 r0 top
C217 "100nF" "CAP 0402/1005 RF" 63.716,321.247 r0 top
C218 "22uF" "CAP 1210/3225 - 1MM" 71.844,312.445 r0 top
C219 "100nF" "CAP 0402/1005 RF" 181.281,358.296 r90 top
C220 "100nF" "CAP 0402/1005 RF" 184.677,358.28 r90 top
C221 "100nF" "CAP 0402/1005 RF" 178.725,358.296 r90 top
C222 "100nF" "CAP 0402/1005 RF" 183.678,358.28 r90 top
C223 "4.7uF" "CAP 0402/1005 RF" 143.407,366.37 r0 top
C224 "470nF" "CAP 0402/1005 RF" 147.155,364.211 r0 top
C225 "470nF" "CAP 0402/1005 RF" 139.671,359.893 r0 top
C226 "68nF" "CAP 0402/1005 RF" 149.753,365.354 r0 top
C227 "68nF" "CAP 0402/1005 RF" 139.662,361.798 r0 top
C228 "4.7uF" "CAP 0402/1005 RF" 147.028,365.227 r0 top
C229 "470nF" "CAP 0402/1005 RF" 149.744,364.211 r0 top
C230 "470nF" "CAP 0402/1005 RF" 139.653,360.909 r0 top
C231 "68nF" "CAP 0402/1005 RF" 139.662,366.37 r0 top
C232 "68nF" "CAP 0402/1005 RF" 143.407,363.957 r0 top
C233 "4.7uF" "CAP 0402/1005 RF" 149.753,362.179 r0 top
C234 "470nF" "CAP 0402/1005 RF" 139.662,365.481 r0 top
C235 "470nF" "CAP 0402/1005 RF" 143.407,362.814 r0 top
C236 "68nF" "CAP 0402/1005 RF" 143.398,365.227 r0 top
C237 "68nF" "CAP 0402/1005 RF" 147.146,363.322 r0 top
C238 "4.7uF" "CAP 0402/1005 RF" 149.744,361.163 r0 top
C239 "470nF" "CAP 0402/1005 RF" 139.662,364.592 r0 top
C240 "470nF" "CAP 0402/1005 RF" 143.407,361.798 r0 top
C241 "68nF" "CAP 0402/1005 RF" 147.155,360.401 r0 top
C242 "68nF" "CAP 0402/1005 RF" 147.155,361.29 r0 top
C243 "100nF" "CAP 0402/1005 RF" 147.155,357.234 r0 top
C244 "100nF" "CAP 0402/1005 RF" 149.762,363.195 r180 top
C245 "100nF" "CAP 0402/1005 RF" 143.345,356.472 r0 top
C246 "100nF" "CAP 0402/1005 RF" 147.155,362.306 r180 top
C247 "4.7uF" "CAP 0402/1005 RF" 139.671,359.004 r0 top
C248 "470nF" "CAP 0402/1005 RF" 150.965,356.218 r0 top
C249 "470nF" "CAP 0402/1005 RF" 149.753,360.147 r0 top
C250 "68nF" "CAP 0402/1005 RF" 139.671,363.703 r0 top
C251 "68nF" "CAP 0402/1005 RF" 143.336,360.655 r0 top
C252 "4.7uF" "CAP 0402/1005 RF" 152.861,361.163 r0 top
C253 "470nF" "CAP 0402/1005 RF" 152.861,363.068 r0 top
C254 "470nF" "CAP 0402/1005 RF" 152.87,363.957 r0 top
C255 "68nF" "CAP 0402/1005 RF" 139.662,362.814 r0 top
C256 "68nF" "CAP 0402/1005 RF" 143.345,359.639 r0 top
C257 "4.7uF" "CAP 0402/1005 RF" 152.861,362.052 r0 top
C258 "470nF" "CAP 0402/1005 RF" 156.036,363.322 r0 top
C259 "470nF" "CAP 0402/1005 RF" 156.163,361.163 r0 top
C260 "68nF" "CAP 0402/1005 RF" 156.036,365.227 r0 top
C261 "68nF" "CAP 0402/1005 RF" 156.036,367.132 r0 top
C262 "4.7uF" "CAP 0402/1005 RF" 156.036,362.306 r0 top
C263 "470nF" "CAP 0402/1005 RF" 156.163,360.147 r0 top
C264 "470nF" "CAP 0402/1005 RF" 156.036,364.211 r0 top
C265 "68nF" "CAP 0402/1005 RF" 156.036,366.116 r0 top
C266 "68nF" "CAP 0402/1005 RF" 152.861,360.147 r0 top
C267 "100nF" "CAP 0201/0603 RF" 374.155,408.05 r270 top
C268 "100nF" "CAP 0201/0603 RF" 373.393,407.923 r270 top
C269 "100nF" "CAP 0201/0603 RF" 371.234,408.298 r270 top
C270 "100nF" "CAP 0201/0603 RF" 370.472,408.31 r270 top
C271 "100nF" "CAP 0201/0603 RF" 229.006,511.285 r90 bottom
C272 "100nF" "CAP 0201/0603 RF" 229.923,511.353 r270 bottom
C273 "10nF" "CAP 0201/0603 RF" 174.671,285.377 r90 top
C274 "100nF" "CAP 0201/0603 RF" 232.816,511.013 r90 bottom
C275 "100nF" "CAP 0201/0603 RF" 287.109,281.403 r90 bottom
C276 "10nF" "CAP 0201/0603 RF" 173.838,285.376 r90 top
C277 "10nF" "CAP 0201/0603 RF" 177.09,280.822 r0 top
C278 "10nF" "CAP 0201/0603 RF" 175.446,280.822 r0 top
C279 "100nF" "CAP 0201/0603 RF" 76.165,331.869 r270 bottom
C280 "100nF" "CAP 0201/0603 RF" 75.415,331.869 r270 bottom
C281 "100nF" "CAP 0201/0603 RF" 73.298,331.869 r270 bottom
C282 "100nF" "CAP 0201/0603 RF" 72.508,331.869 r270 bottom
C283 "100nF" "CAP 0201/0603 RF" 67.338,325.38 r90 bottom
C284 "100nF" "CAP 0201/0603 RF" 68.081,325.38 r90 bottom
C285 "10nF" "CAP 0201/0603 RF" 173.147,285.377 r90 top
C286 "100nF" "CAP 0201/0603 RF" 70.04,325.38 r90 bottom
C287 "100nF" "CAP 0201/0603 RF" 70.725,325.38 r90 bottom
C288 "10nF" "CAP 0201/0603 RF" 175.433,285.377 r90 top
C289 "10nF" "CAP 0201/0603 RF" 157.569,299.149 r0 top
C290 "10nF" "CAP 0201/0603 RF" 155.976,299.069 r0 top
C291 "100nF" "CAP 0201/0603 RF" 192.113,211.867 r90 bottom
C292 "100nF" "CAP 0201/0603 RF" 192.875,211.867 r90 bottom
C293 "100nF" "CAP 0201/0603 RF" 195.161,211.867 r90 bottom
C294 "100nF" "CAP 0201/0603 RF" 195.923,211.867 r90 bottom
C295 "100nF" "CAP 0201/0603 RF" 198.875,211.867 r90 bottom
C296 "100nF" "CAP 0201/0603 RF" 198.113,211.867 r90 bottom
C297 "10nF" "CAP 0201/0603 RF" 171.539,285.388 r90 top
C298 "100nF" "CAP 0201/0603 RF" 201.945,211.867 r90 bottom
C299 "100nF" "CAP 0201/0603 RF" 201.183,211.867 r90 bottom
C300 "10nF" "CAP 0201/0603 RF" 172.301,285.388 r90 top
C301 "10nF" "CAP 0201/0603 RF" 157.569,300.546 r0 top
C302 "10nF" "CAP 0201/0603 RF" 155.976,300.466 r0 top
C303_I2C_Bridge "100nF" "CAP 0402/1005 RF" 365.392,71.231 r90 top (schematic designator C303)
C303_I2C_Bridge_2 "100nF" "CAP 0402/1005 RF" 1127.493,244.297 r90 top (schematic designator C303)
C303_I2C_Bridge_3 "100nF" "CAP 0402/1005 RF" 360.832,81.026 r90 top (schematic designator C303)
C304 "4.7µF" "CAP 0603/1608 RF" 447.942,34.836 r0 top
C305 "4.7µF" "CAP 0603/1608 RF" 452.26,34.836 r0 top
C306 "4.7µF" "CAP 0603/1608 RF" 456.578,34.836 r0 top
C307 "4.7µF" "CAP 0603/1608 RF" 460.896,34.836 r0 top
C308 "4.7 µF" "CAP 0603/1608 RF" 434.988,34.836 r0 top
C309_U_Pomiar_pradu_napiecia_1 "100nF" "CAP 0402/1005 RF" 360.832,136.677 r90 top (schematic designator C309)
C309_U_Pomiar_pradu_napiecia_2 "100nF" "CAP 0402/1005 RF" 359.74,144.301 r90 top (schematic designator C309)
C309_U_Pomiar_pradu_napiecia_3 "100nF" "CAP 0402/1005 RF" 360.832,149.631 r90 top (schematic designator C309)
C309_U_Pomiar_pradu_napiecia_4 "100nF" "CAP 0402/1005 RF" 360.832,156.108 r90 top (schematic designator C309)
C309_U_Pomiar_pradu_napiecia_5 "100nF" "CAP 0402/1005 RF" 362.585,160.004 r90 top (schematic designator C309)
C309_U_Pomiar_pradu_napiecia_6 "100nF" "CAP 0402/1005 RF" 362.928,167.852 r90 top (schematic designator C309)
C309_U_Pomiar_pradu_napiecia_7 "100nF" "CAP 0402/1005 RF" 360.832,175.539 r90 top (schematic designator C309)
C309_U_Pomiar_pradu_napiecia_8 "100nF" "CAP 0402/1005 RF" 360.832,182.016 r90 top (schematic designator C309)
C309_U_Pomiar_pradu_napiecia_9 "100nF" "CAP 0402/1005 RF" 360.832,188.493 r90 top (schematic designator C309)
C309_U_Pomiar_pradu_napiecia_10 "100nF" "CAP 0402/1005 RF" 362.61,195.139 r90 top (schematic designator C309)
C309_U_Pomiar_pradu_napiecia_11 "100nF" "CAP 0402/1005 RF" 362.915,202.053 r90 top (schematic designator C309)
C310 "100nF" "CAP 0402/1005 RF" 360.832,47.447 r90 top
C311_I2C_Expander1 "1uF" "CAP 0402/1005 RF" 360.832,65.43 r90 top (schematic designator C311)
C311_I2C_Expander2 "1uF" "CAP 0402/1005 RF" 363.353,68.386 r90 top (schematic designator C311)
C311_I2C_Expander3 "1uF" "CAP 0402/1005 RF" 360.832,78.384 r90 top (schematic designator C311)
C311_I2C_Expander? "1uF" "CAP 0402/1005 RF" 360.832,84.861 r90 top (schematic designator C311)
C311_I2C_Expander_10 "1uF" "CAP 0402/1005 RF" 360.832,91.338 r90 top (schematic designator C311)
C311_I2C_Expander_11 "1uF" "CAP 0402/1005 RF" 360.832,97.815 r90 top (schematic designator C311)
C311_I2C_Expander_12 "1uF" "CAP 0402/1005 RF" 360.832,104.292 r90 top (schematic designator C311)
C311_I2C_Expander_13 "1uF" "CAP 0402/1005 RF" 360.832,110.769 r90 top (schematic designator C311)
C311_I2C_Expander_14 "1uF" "CAP 0402/1005 RF" 362.42,116.9 r90 top (schematic designator C311)
C311_I2C_Expander_15 "1uF" "CAP 0402/1005 RF" 360.832,123.723 r90 top (schematic designator C311)
C311_I2C_Expander_16 "1uF" "CAP 0402/1005 RF" 360.705,128.19 r90 top (schematic designator C311)
C320 "10nF" "CAP 0402/1005 RF" 134.226,404.297 r270 top
C321 "3.3nF" "CAP 0603/1608 RF" 132.118,408.488 r180 top
C322 "27pF" "CAP 0402/1005 RF" 130.139,397.947 r180 top
C323 "27pF" "CAP 0402/1005 RF" 128.159,397.947 r0 top
C324 "10uF" "CAP 0805/2012 RF" 290.538,154.203 r90 top
C325 "100nF" "CAP 0402/1005 RF" 219.445,278.037 r270 top
C326 "1uF" "CAP 0402/1005 RF" 261.455,154.711 r90 top
C327 "1uF" "CAP 0402/1005 RF" 267.297,154.711 r90 top
C328 "1uF" "CAP 0402/1005 RF" 273.139,154.711 r90 top
C329 "1uF" "CAP 0402/1005 RF" 278.981,154.711 r90 top
C330 "100nF" "CAP 0402/1005 RF" 218.244,278.037 r270 top
C331 "1uF" "CAP 0402/1005 RF" 202.324,295.961 r270 top
C332 "1uF" "CAP 0402/1005 RF" 204.267,301.135 r0 top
